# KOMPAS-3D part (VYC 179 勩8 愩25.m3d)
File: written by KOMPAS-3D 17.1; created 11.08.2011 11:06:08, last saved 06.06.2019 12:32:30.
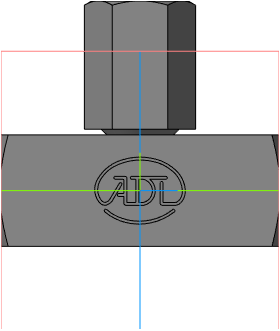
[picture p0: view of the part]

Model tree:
1. Плоскость XY
2. Плоскость ZX
3. Плоскость ZY
4. Ось X
5. Ось Y
6. Ось Z
7. Начало координат
8. Операция без истории:2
